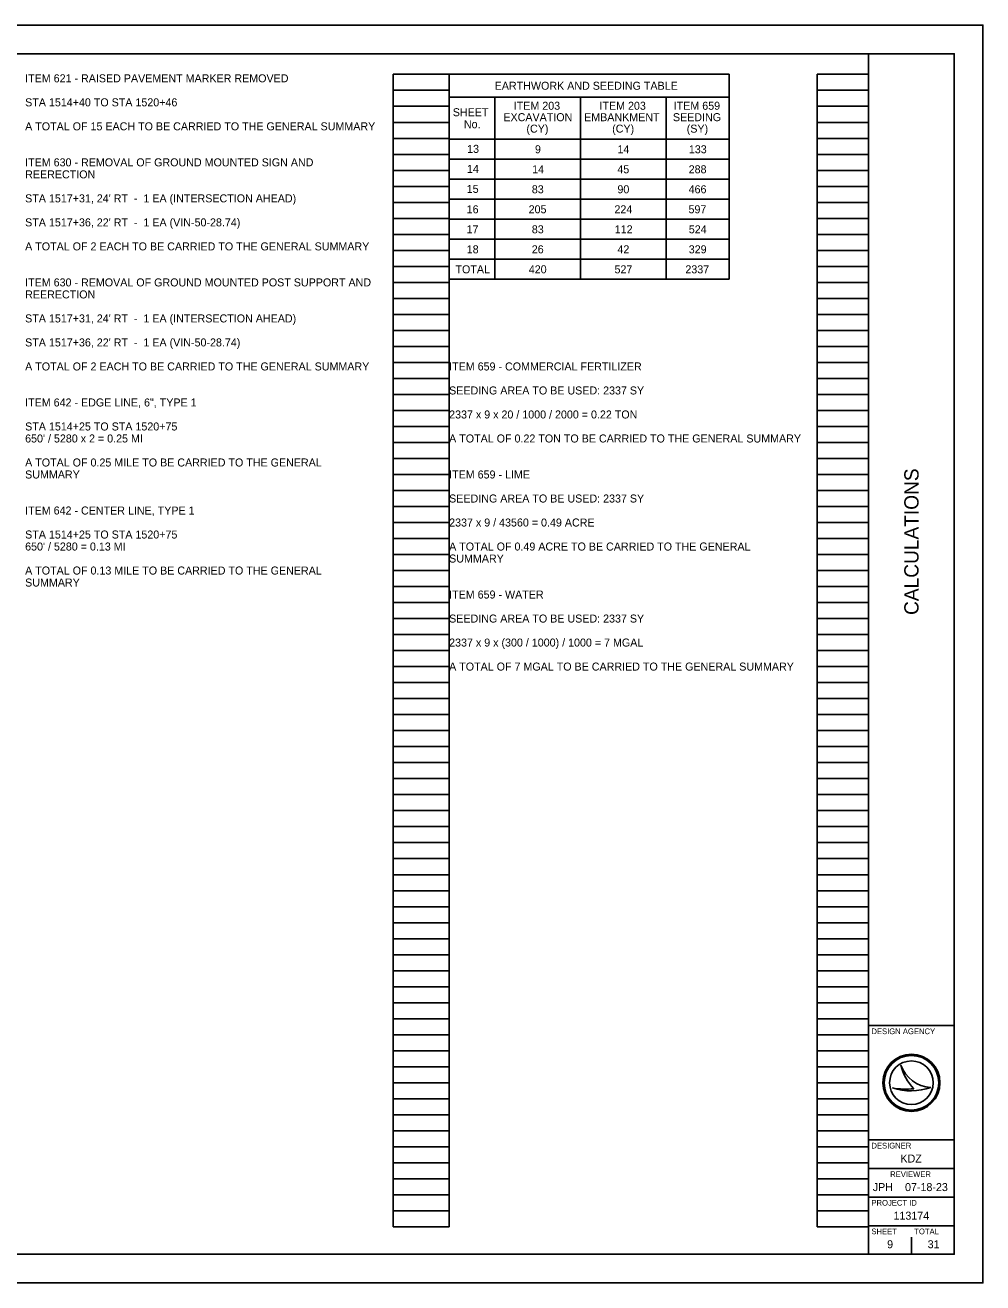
# Model space of a CAD drawing. Extents: x 0 to 34, y 0 to 22.
# Drawn here: x 17.24 to 34, y 0 to 22 of the extents above; entities that cross this region are included whole.
import ezdxf

# ---------------------------------------------------------------- set-up
doc = ezdxf.new("R2010")
doc.units = 0
for name, color, linetype in [('SH_Border', 7, 'Continuous'), ('SH_Cut_Line', 7, 'Continuous'), ('SH_Data', 7, 'Continuous'), ('SH_Text', 7, 'Continuous'), ('TX_P_1', 7, 'Continuous')]:
    doc.layers.add(name, color=color, linetype=linetype)

msp = doc.modelspace()

# ---------------------------------------------------------------- linework, layer by layer
at = {"layer": 'SH_Border'}
for p, q in [((32, 0.5), (32, 21.5)), ((32, 4.5), (33.5, 4.5)), ((32, 2.5), (33.5, 2.5)), ((32, 2), (33.5, 2)), ((32, 1.5), (33.5, 1.5)), ((32, 1), (33.5, 1))]:
    msp.add_line(p, q, dxfattribs=at)
msp.add_lwpolyline([(1.5, 21.5), (33.5, 21.5), (33.5, 0.5), (1.5, 0.5)], close=True, dxfattribs=at)
at = {"layer": 'SH_Cut_Line'}
msp.add_lwpolyline([(0, 0), (34, 0), (34, 22), (0, 22)], close=True, dxfattribs=at)
at = {"layer": 'SH_Data'}
for p, q in [((23.68, 0.98), (23.68, 21.14)), ((23.68, 21.14), (24.66, 21.14)), ((24.66, 0.98), (24.66, 21.14)), ((31.1, 0.98), (31.1, 21.14)), ((31.1, 21.14), (32, 21.14)), ((32, 0.98), (32, 21.14)), ((23.68, 20.86), (24.66, 20.86)), ((31.1, 20.86), (32, 20.86)), ((23.68, 20.58), (24.66, 20.58)), ((31.1, 20.58), (32, 20.58)), ((23.68, 20.3), (24.66, 20.3)), ((31.1, 20.3), (32, 20.3)), ((23.68, 20.02), (24.66, 20.02)), ((31.1, 20.02), (32, 20.02)), ((23.68, 19.74), (24.66, 19.74)), ((31.1, 19.74), (32, 19.74)), ((23.68, 19.46), (24.66, 19.46)), ((31.1, 19.46), (32, 19.46)), ((23.68, 19.18), (24.66, 19.18)), ((31.1, 19.18), (32, 19.18)), ((23.68, 18.9), (24.66, 18.9)), ((31.1, 18.9), (32, 18.9)), ((23.68, 18.62), (24.66, 18.62)), ((31.1, 18.62), (32, 18.62)), ((23.68, 18.34), (24.66, 18.34)), ((31.1, 18.34), (32, 18.34)), ((23.68, 18.06), (24.66, 18.06)), ((31.1, 18.06), (32, 18.06)), ((23.68, 17.78), (24.66, 17.78)), ((31.1, 17.78), (32, 17.78)), ((23.68, 17.5), (24.66, 17.5)), ((31.1, 17.5), (32, 17.5)), ((23.68, 17.22), (24.66, 17.22)), ((31.1, 17.22), (32, 17.22)), ((23.68, 16.94), (24.66, 16.94)), ((31.1, 16.94), (32, 16.94)), ((23.68, 16.66), (24.66, 16.66)), ((31.1, 16.66), (32, 16.66)), ((23.68, 16.38), (24.66, 16.38)), ((31.1, 16.38), (32, 16.38)), ((23.68, 16.1), (24.66, 16.1)), ((31.1, 16.1), (32, 16.1)), ((23.68, 15.82), (24.66, 15.82)), ((31.1, 15.82), (32, 15.82)), ((23.68, 15.54), (24.66, 15.54)), ((31.1, 15.54), (32, 15.54)), ((23.68, 15.26), (24.66, 15.26)), ((31.1, 15.26), (32, 15.26)), ((23.68, 14.98), (24.66, 14.98)), ((31.1, 14.98), (32, 14.98)), ((23.68, 14.7), (24.66, 14.7)), ((31.1, 14.7), (32, 14.7)), ((23.68, 14.42), (24.66, 14.42)), ((31.1, 14.42), (32, 14.42)), ((23.68, 14.14), (24.66, 14.14)), ((31.1, 14.14), (32, 14.14)), ((23.68, 13.86), (24.66, 13.86)), ((31.1, 13.86), (32, 13.86)), ((23.68, 13.58), (24.66, 13.58)), ((31.1, 13.58), (32, 13.58)), ((23.68, 13.3), (24.66, 13.3)), ((31.1, 13.3), (32, 13.3)), ((23.68, 13.02), (24.66, 13.02)), ((31.1, 13.02), (32, 13.02)), ((23.68, 12.74), (24.66, 12.74)), ((31.1, 12.74), (32, 12.74)), ((23.68, 12.46), (24.66, 12.46)), ((31.1, 12.46), (32, 12.46)), ((23.68, 12.18), (24.66, 12.18)), ((31.1, 12.18), (32, 12.18)), ((23.68, 11.9), (24.66, 11.9)), ((31.1, 11.9), (32, 11.9)), ((23.68, 11.62), (24.66, 11.62)), ((31.1, 11.62), (32, 11.62)), ((23.68, 11.34), (24.66, 11.34)), ((31.1, 11.34), (32, 11.34)), ((23.68, 11.06), (24.66, 11.06)), ((31.1, 11.06), (32, 11.06)), ((23.68, 10.78), (24.66, 10.78)), ((31.1, 10.78), (32, 10.78)), ((23.68, 10.5), (24.66, 10.5)), ((31.1, 10.5), (32, 10.5)), ((23.68, 10.22), (24.66, 10.22)), ((31.1, 10.22), (32, 10.22)), ((23.68, 9.94), (24.66, 9.94)), ((31.1, 9.94), (32, 9.94)), ((23.68, 9.66), (24.66, 9.66)), ((31.1, 9.66), (32, 9.66)), ((23.68, 9.38), (24.66, 9.38)), ((31.1, 9.38), (32, 9.38)), ((23.68, 9.1), (24.66, 9.1)), ((31.1, 9.1), (32, 9.1)), ((23.68, 8.82), (24.66, 8.82)), ((31.1, 8.82), (32, 8.82)), ((23.68, 8.54), (24.66, 8.54)), ((31.1, 8.54), (32, 8.54)), ((23.68, 8.26), (24.66, 8.26)), ((31.1, 8.26), (32, 8.26)), ((23.68, 7.98), (24.66, 7.98)), ((31.1, 7.98), (32, 7.98)), ((23.68, 7.7), (24.66, 7.7)), ((31.1, 7.7), (32, 7.7)), ((23.68, 7.42), (24.66, 7.42)), ((31.1, 7.42), (32, 7.42)), ((23.68, 7.14), (24.66, 7.14)), ((31.1, 7.14), (32, 7.14)), ((23.68, 6.86), (24.66, 6.86)), ((31.1, 6.86), (32, 6.86)), ((23.68, 6.58), (24.66, 6.58)), ((31.1, 6.58), (32, 6.58)), ((23.68, 6.3), (24.66, 6.3)), ((31.1, 6.3), (32, 6.3)), ((23.68, 6.02), (24.66, 6.02)), ((31.1, 6.02), (32, 6.02)), ((23.68, 5.74), (24.66, 5.74)), ((31.1, 5.74), (32, 5.74)), ((23.68, 5.46), (24.66, 5.46)), ((31.1, 5.46), (32, 5.46)), ((23.68, 5.18), (24.66, 5.18)), ((31.1, 5.18), (32, 5.18)), ((23.68, 4.9), (24.66, 4.9)), ((31.1, 4.9), (32, 4.9)), ((23.68, 4.62), (24.66, 4.62)), ((31.1, 4.62), (32, 4.62)), ((23.68, 4.34), (24.66, 4.34)), ((31.1, 4.34), (32, 4.34)), ((23.68, 4.06), (24.66, 4.06)), ((31.1, 4.06), (32, 4.06)), ((23.68, 3.78), (24.66, 3.78)), ((31.1, 3.78), (32, 3.78)), ((32.567, 3.81), (32.567, 3.81)), ((23.68, 3.5), (24.66, 3.5)), ((31.1, 3.5), (32, 3.5)), ((32.417, 3.41), (32.417, 3.41)), ((32.75, 3.5), (32.75, 3.5)), ((33.087, 3.419), (33.087, 3.419)), ((23.68, 3.22), (24.66, 3.22)), ((31.1, 3.22), (32, 3.22)), ((23.68, 2.94), (24.66, 2.94)), ((31.1, 2.94), (32, 2.94)), ((23.68, 2.66), (24.66, 2.66)), ((31.1, 2.66), (32, 2.66)), ((23.68, 2.38), (24.66, 2.38)), ((31.1, 2.38), (32, 2.38)), ((23.68, 2.1), (24.66, 2.1)), ((31.1, 2.1), (32, 2.1)), ((23.68, 1.82), (24.66, 1.82)), ((31.1, 1.82), (32, 1.82)), ((23.68, 1.54), (24.66, 1.54)), ((31.1, 1.54), (32, 1.54)), ((23.68, 1.26), (24.66, 1.26)), ((31.1, 1.26), (32, 1.26)), ((23.68, 0.98), (24.66, 0.98)), ((31.1, 0.98), (32, 0.98)), ((32.375, 0.675), (32.375, 0.675)), ((32.75, 0.5), (32.75, 0.8))]:
    msp.add_line(p, q, dxfattribs=at)
for radius in [0.5, 0.477, 0.477, 0.382]:
    msp.add_circle((32.75, 3.5), radius, dxfattribs=at)
for centre, radius, start, end in [((33.116, 3.998), 0.58, 198.9257, 198.9319), ((33.347, 3.97), 0.796, 191.6379, 191.6421), ((33.116, 3.998), 0.58, 198.9319, 267.1657), ((33.347, 3.97), 0.796, 191.6421, 226.0947), ((32.739, 4.37), 1.013, 251.4576, 290.0832), ((32.648, 4.654), 1.266, 259.4964, 259.4995), ((32.739, 4.37), 1.013, 251.4527, 251.4576), ((32.648, 4.654), 1.266, 259.4995, 276.6672)]:
    msp.add_arc(centre, radius, start, end, dxfattribs=at)
at = {"layer": 'TX_P_1'}
for p, q in [((29.56, 21.14), (24.66, 21.14)), ((24.66, 21.14), (24.66, 17.554)), ((29.56, 21.14), (29.56, 17.554)), ((29.56, 20.74), (24.66, 20.74)), ((25.46, 20.74), (25.46, 17.554)), ((26.96, 20.74), (26.96, 17.554)), ((28.46, 20.74), (28.46, 17.554)), ((29.56, 20.004), (24.66, 20.004)), ((29.56, 19.654), (24.66, 19.654)), ((29.56, 19.304), (24.66, 19.304)), ((29.56, 18.954), (24.66, 18.954)), ((29.56, 18.604), (24.66, 18.604)), ((29.56, 18.254), (24.66, 18.254)), ((29.56, 17.904), (24.66, 17.904)), ((29.56, 17.554), (24.66, 17.554))]:
    msp.add_line(p, q, dxfattribs=at)

# ---------------------------------------------------------------- texts
at = {"layer": 'SH_Data'}
msp.add_text('CALCULATIONS', height=0.25, rotation=90, dxfattribs=at).set_placement((32.875, 11.683))
for s, height, p in [('DESIGN AGENCY', 0.1, (32.05, 4.35)), ('DESIGNER', 0.1, (32.05, 2.35)), ('KDZ', 0.14, (32.557, 2.105)), ('REVIEWER', 0.1, (32.378, 1.85)), ('JPH', 0.14, (32.073, 1.605)), ('07-18-23', 0.14, (32.638, 1.605)), ('PROJECT ID', 0.1, (32.05, 1.35)), ('113174', 0.14, (32.436, 1.105)), ('SHEET', 0.1, (32.05, 0.85)), ('TOTAL', 0.1, (32.8, 0.85)), ('9', 0.14, (32.325, 0.605)), ('31', 0.14, (33.034, 0.605))]:
    msp.add_text(s, height=height, dxfattribs=at).set_placement(p)
at = {"layer": 'SH_Text'}
for s, p in [('ITEM 621 - RAISED PAVEMENT MARKER REMOVED', (17.24, 21)), ('STA 1514+40 TO STA 1520+46', (17.24, 20.58)), ('A TOTAL OF 15 EACH TO BE CARRIED TO THE GENERAL SUMMARY', (17.24, 20.16)), ('ITEM 630 - REMOVAL OF GROUND MOUNTED SIGN AND ', (17.24, 19.53)), ('REERECTION', (17.24, 19.32)), ("STA 1517+31, 24' RT  -  1 EA (INTERSECTION AHEAD)", (17.24, 18.9)), ("STA 1517+36, 22' RT  -  1 EA (VIN-50-28.74)", (17.24, 18.48)), ('A TOTAL OF 2 EACH TO BE CARRIED TO THE GENERAL SUMMARY', (17.24, 18.06)), ('ITEM 630 - REMOVAL OF GROUND MOUNTED POST SUPPORT AND ', (17.24, 17.43)), ('REERECTION', (17.24, 17.22)), ("STA 1517+31, 24' RT  -  1 EA (INTERSECTION AHEAD)", (17.24, 16.8)), ("STA 1517+36, 22' RT  -  1 EA (VIN-50-28.74)", (17.24, 16.38)), ('A TOTAL OF 2 EACH TO BE CARRIED TO THE GENERAL SUMMARY', (17.24, 15.96)), ('ITEM 659 - COMMERCIAL FERTILIZER', (24.66, 15.96)), ('SEEDING AREA TO BE USED: 2337 SY', (24.66, 15.54)), ('ITEM 642 - EDGE LINE, 6", TYPE 1', (17.24, 15.33)), ('2337 x 9 x 20 / 1000 / 2000 = 0.22 TON', (24.66, 15.12)), ('STA 1514+25 TO STA 1520+75', (17.24, 14.91)), ("650' / 5280 x 2 = 0.25 MI", (17.24, 14.7)), ('A TOTAL OF 0.22 TON TO BE CARRIED TO THE GENERAL SUMMARY', (24.66, 14.7)), ('A TOTAL OF 0.25 MILE TO BE CARRIED TO THE GENERAL ', (17.24, 14.28)), ('SUMMARY', (17.24, 14.07)), ('ITEM 659 - LIME', (24.66, 14.07)), ('SEEDING AREA TO BE USED: 2337 SY', (24.66, 13.65)), ('ITEM 642 - CENTER LINE, TYPE 1', (17.24, 13.44)), ('2337 x 9 / 43560 = 0.49 ACRE', (24.66, 13.23)), ('STA 1514+25 TO STA 1520+75', (17.24, 13.02)), ("650' / 5280 = 0.13 MI", (17.24, 12.81)), ('A TOTAL OF 0.49 ACRE TO BE CARRIED TO THE GENERAL ', (24.66, 12.81)), ('SUMMARY', (24.66, 12.6)), ('A TOTAL OF 0.13 MILE TO BE CARRIED TO THE GENERAL ', (17.24, 12.39)), ('SUMMARY', (17.24, 12.18)), ('ITEM 659 - WATER', (24.66, 11.97)), ('SEEDING AREA TO BE USED: 2337 SY', (24.66, 11.55)), ('2337 x 9 x (300 / 1000) / 1000 = 7 MGAL', (24.66, 11.13)), ('A TOTAL OF 7 MGAL TO BE CARRIED TO THE GENERAL SUMMARY', (24.66, 10.71))]:
    msp.add_text(s, height=0.14, dxfattribs=at).set_placement(p)
at = {"layer": 'TX_P_1'}
for s, p in [('EARTHWORK AND SEEDING TABLE', (25.457, 20.87)), ('SHEET', (24.724, 20.407)), ('EXCAVATION', (25.609, 20.32)), ('ITEM 203', (25.791, 20.52)), ('EMBANKMENT', (27.022, 20.32)), ('ITEM 203', (27.291, 20.52)), ('SEEDING', (28.576, 20.32)), ('ITEM 659', (28.59, 20.52)), ('No.', (24.918, 20.197)), ('(CY)', (26.013, 20.12)), ('(CY)', (27.513, 20.12)), ('(SY)', (28.818, 20.12)), ('13', (24.975, 19.766)), ('9', (26.162, 19.759)), ('14', (27.606, 19.759)), ('133', (28.855, 19.759)), ('14', (24.972, 19.416)), ('14', (26.113, 19.409)), ('45', (27.604, 19.409)), ('288', (28.852, 19.409)), ('15', (24.968, 19.066)), ('83', (26.107, 19.059)), ('90', (27.605, 19.059)), ('466', (28.851, 19.059)), ('16', (24.967, 18.709)), ('205', (26.051, 18.709)), ('224', (27.553, 18.709)), ('597', (28.849, 18.709)), ('17', (24.965, 18.359)), ('83', (26.107, 18.359)), ('112', (27.558, 18.359)), ('524', (28.854, 18.359)), ('18', (24.968, 18.009)), ('26', (26.106, 18.009)), ('42', (27.605, 18.009)), ('329', (28.853, 18.009)), ('TOTAL', (24.771, 17.659)), ('420', (26.054, 17.659)), ('527', (27.554, 17.659)), ('2337', (28.794, 17.659))]:
    msp.add_text(s, height=0.14, dxfattribs=at).set_placement(p)

doc.saveas('drawing.dxf')
